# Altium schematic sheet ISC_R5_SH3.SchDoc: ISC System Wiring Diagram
size B; DrawnBy: Filiberto Clara; Engineer: Filiberto Clara; Organization: LIGO Laboratory; Address1: California Institute of Technology; Address2: Massachusetts Institute of Technology; SheetNumber: 21; SheetTotal: 39
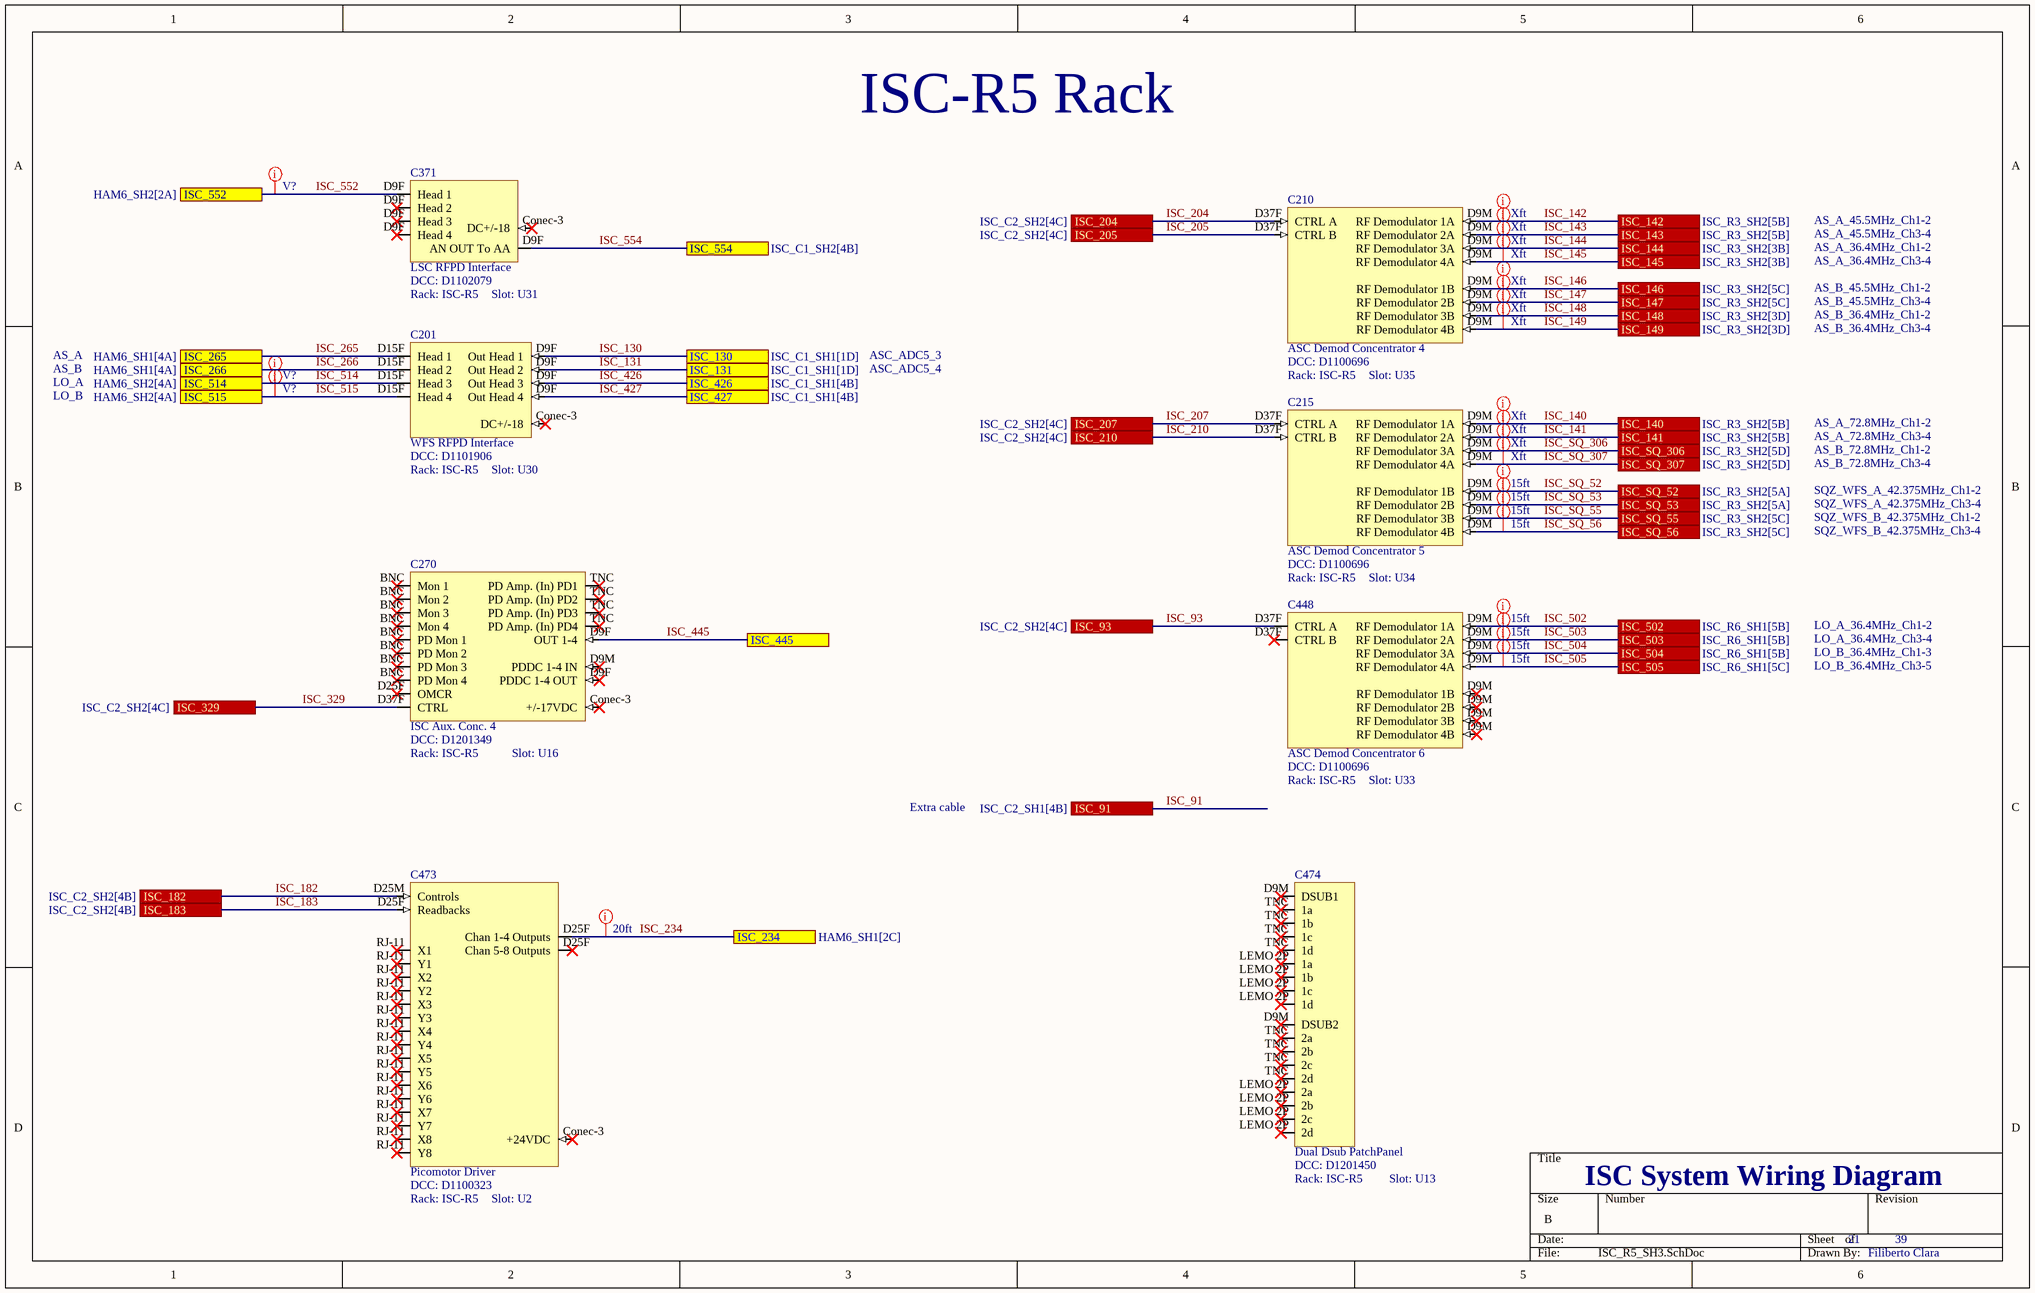
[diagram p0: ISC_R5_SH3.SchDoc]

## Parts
C201  WFS RFPD Interface  DCC: D1101906  Rack: ISC-R5  Slot: U30
C210  ASC Demod Concentrator 4  DCC: D1100696  Rack: ISC-R5  Slot: U35
C215  ASC Demod Concentrator 5  DCC: D1100696  Rack: ISC-R5  Slot: U34
C270  ISC Aux. Conc. 4  DCC: D1201349  Rack: ISC-R5  Slot: U16
C371  LSC RFPD Interface  DCC: D1102079  Rack: ISC-R5  Slot: U31
C448  ASC Demod Concentrator 6  DCC: D1100696  Rack: ISC-R5  Slot: U33
C473  Picomotor Driver  DCC: D1100323  Rack: ISC-R5  Slot: U2
C474  Dual Dsub PatchPanel  DCC: D1201450  Rack: ISC-R5  Slot: U13

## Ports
ISC_91 (see ISC_C2_SH1[4B]), ISC_93 (see ISC_C2_SH2[4C]), ISC_130 (see ISC_C1_SH1[1D]), ISC_131 (see ISC_C1_SH1[1D]), ISC_140 (see ISC_R3_SH2[5B]), ISC_141 (see ISC_R3_SH2[5B]), ISC_142 (see ISC_R3_SH2[5B]), ISC_143 (see ISC_R3_SH2[5B]), ISC_144 (see ISC_R3_SH2[3B]), ISC_145 (see ISC_R3_SH2[3B]), ISC_146 (see ISC_R3_SH2[5C]), ISC_147 (see ISC_R3_SH2[5C]), ISC_148 (see ISC_R3_SH2[3D]), ISC_149 (see ISC_R3_SH2[3D]), ISC_182 (see ISC_C2_SH2[4B]), ISC_183 (see ISC_C2_SH2[4B]), ISC_204 (see ISC_C2_SH2[4C]), ISC_205 (see ISC_C2_SH2[4C]), ISC_207 (see ISC_C2_SH2[4C]), ISC_210 (see ISC_C2_SH2[4C]), ISC_234 (see HAM6_SH1[2C]), ISC_265 (see HAM6_SH1[4A]), ISC_266 (see HAM6_SH1[4A]), ISC_329 (see ISC_C2_SH2[4C]), ISC_426 (see ISC_C1_SH1[4B]), ISC_427 (see ISC_C1_SH1[4B]), ISC_445, ISC_502 (see ISC_R6_SH1[5B]), ISC_503 (see ISC_R6_SH1[5B]), ISC_504 (see ISC_R6_SH1[5B]), ISC_505 (see ISC_R6_SH1[5C]), ISC_514 (see HAM6_SH2[4A]), ISC_515 (see HAM6_SH2[4A]), ISC_552 (see HAM6_SH2[2A]), ISC_554 (see ISC_C1_SH2[4B]), ISC_SQ_52 (see ISC_R3_SH2[5A]), ISC_SQ_53 (see ISC_R3_SH2[5A]), ISC_SQ_55 (see ISC_R3_SH2[5C]), ISC_SQ_56 (see ISC_R3_SH2[5C]), ISC_SQ_306 (see ISC_R3_SH2[5D]), ISC_SQ_307 (see ISC_R3_SH2[5D])

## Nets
ISC_93: C448.D37F(CTRL_A) ; port ISC_93
ISC_130: C201.D9F(Out_Head_1) ; port ISC_130
ISC_131: C201.D9F(Out_Head_2) ; port ISC_131
ISC_140: C215.D9M(RF_Demodulator_1A) ; port ISC_140
ISC_141: C215.D9M(RF_Demodulator_2A) ; port ISC_141
ISC_142: C210.D9M(RF_Demodulator_1A) ; port ISC_142
ISC_143: C210.D9M(RF_Demodulator_2A) ; port ISC_143
ISC_144: C210.D9M(RF_Demodulator_3A) ; port ISC_144
ISC_145: C210.D9M(RF_Demodulator_4A) ; port ISC_145
ISC_146: C210.D9M(RF_Demodulator_1B) ; port ISC_146
ISC_147: C210.D9M(RF_Demodulator_2B) ; port ISC_147
ISC_148: C210.D9M(RF_Demodulator_3B) ; port ISC_148
ISC_149: C210.D9M(RF_Demodulator_4B) ; port ISC_149
ISC_182: C473.D25M(Controls) ; port ISC_182
ISC_183: C473.D25F(Readbacks) ; port ISC_183
ISC_204: C210.D37F(CTRL_A) ; port ISC_204
ISC_205: C210.D37F(CTRL_B) ; port ISC_205
ISC_207: C215.D37F(CTRL_A) ; port ISC_207
ISC_210: C215.D37F(CTRL_B) ; port ISC_210
ISC_234: C473.D25F(Chan_1-4_Outputs) ; port ISC_234
ISC_265: C201.D15F(Head_1) ; port ISC_265
ISC_266: C201.D15F(Head_2) ; port ISC_266
ISC_329: C270.D37F(CTRL) ; port ISC_329
ISC_426: C201.D9F(Out_Head_3) ; port ISC_426
ISC_427: C201.D9F(Out_Head_4) ; port ISC_427
ISC_445: C270.D9F(PDDC_1-4_OUT) ; port ISC_445
ISC_502: C448.D9M(RF_Demodulator_1A) ; port ISC_502
ISC_503: C448.D9M(RF_Demodulator_2A) ; port ISC_503
ISC_504: C448.D9M(RF_Demodulator_3A) ; port ISC_504
ISC_505: C448.D9M(RF_Demodulator_4A) ; port ISC_505
ISC_514: C201.D15F(Head_3) ; port ISC_514
ISC_515: C201.D15F(Head_4) ; port ISC_515
ISC_552: C371.D9F(Head_1) ; port ISC_552
ISC_554: C371.D9F(AN_OUT_To_AA) ; port ISC_554
ISC_SQ_52: C215.D9M(RF_Demodulator_1B) ; port ISC_SQ_52
ISC_SQ_53: C215.D9M(RF_Demodulator_2B) ; port ISC_SQ_53
ISC_SQ_55: C215.D9M(RF_Demodulator_3B) ; port ISC_SQ_55
ISC_SQ_56: C215.D9M(RF_Demodulator_4B) ; port ISC_SQ_56
ISC_SQ_306: C215.D9M(RF_Demodulator_3A) ; port ISC_SQ_306
ISC_SQ_307: C215.D9M(RF_Demodulator_4A) ; port ISC_SQ_307

Not connected (* = marked no-connect by the designer): C201 Conec-3(DC+/-18)*; C270 BNC(PD_Mon_1)* Conec-3(+/-17VDC)* D9M(PDDC_1-4_IN)* D25F(OMCR)* TNC(PD_Amp._(In)_PD1)*; C371 Conec-3(DC+/-18)*; C473 Conec-3(+24VDC)* RJ-11(X1)*; C474 D9M(DSUB1)* LEMO 2P(1a)* TNC(1a)*

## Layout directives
Length: V?: ISC_514, ISC_515, ISC_552
Length: 20ft: ISC_234
Length: 15ft: ISC_502, ISC_503, ISC_504, ISC_505, ISC_SQ_52, ISC_SQ_53, ISC_SQ_55, ISC_SQ_56
Length: Xft: ISC_140, ISC_141, ISC_142, ISC_143, ISC_144, ISC_145, ISC_146, ISC_147, ISC_148, ISC_149, ISC_SQ_306, ISC_SQ_307

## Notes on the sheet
- ISC-R5 Rack
- AS_A_45.5MHz_Ch1-2
- AS_A_45.5MHz_Ch3-4
- AS_A_36.4MHz_Ch1-2
- AS_A_36.4MHz_Ch3-4
- AS_B_45.5MHz_Ch1-2
- AS_A
- AS_B
- ASC_ADC5_3
- ASC_ADC5_4
- AS_B_45.5MHz_Ch3-4
- AS_B_36.4MHz_Ch1-2
- AS_B_36.4MHz_Ch3-4
- LO_A
- LO_B
- AS_A_72.8MHz_Ch1-2
- AS_A_72.8MHz_Ch3-4
- AS_B_72.8MHz_Ch1-2
- AS_B_72.8MHz_Ch3-4
- SQZ_WFS_A_42.375MHz_Ch1-2
- SQZ_WFS_A_42.375MHz_Ch3-4
- SQZ_WFS_B_42.375MHz_Ch1-2
- SQZ_WFS_B_42.375MHz_Ch3-4
- LO_A_36.4MHz_Ch1-2
- LO_A_36.4MHz_Ch3-4
- LO_B_36.4MHz_Ch1-3
- LO_B_36.4MHz_Ch3-5
- Extra cable

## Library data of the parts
C201 = WFS RFPD Interface: Serial: Sxxxxxxx; System: ISC
C210 C215 C448 = ASC Demod Concentrator: Serial: Sxxxxxxx; System: ISC
C270 = ISC Aux. Conc. 4: Serial: Sxxxxxxx
C371 = LSC RFPD Interface: Serial: Sxxxxxxx; System: ISC
C473 = Picomotor Driver: Serial: Sxxxxxxx; System: ISC
C474 = Dual Dsub PatchPanel: Serial: Sxxxxxxx; System: ISC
